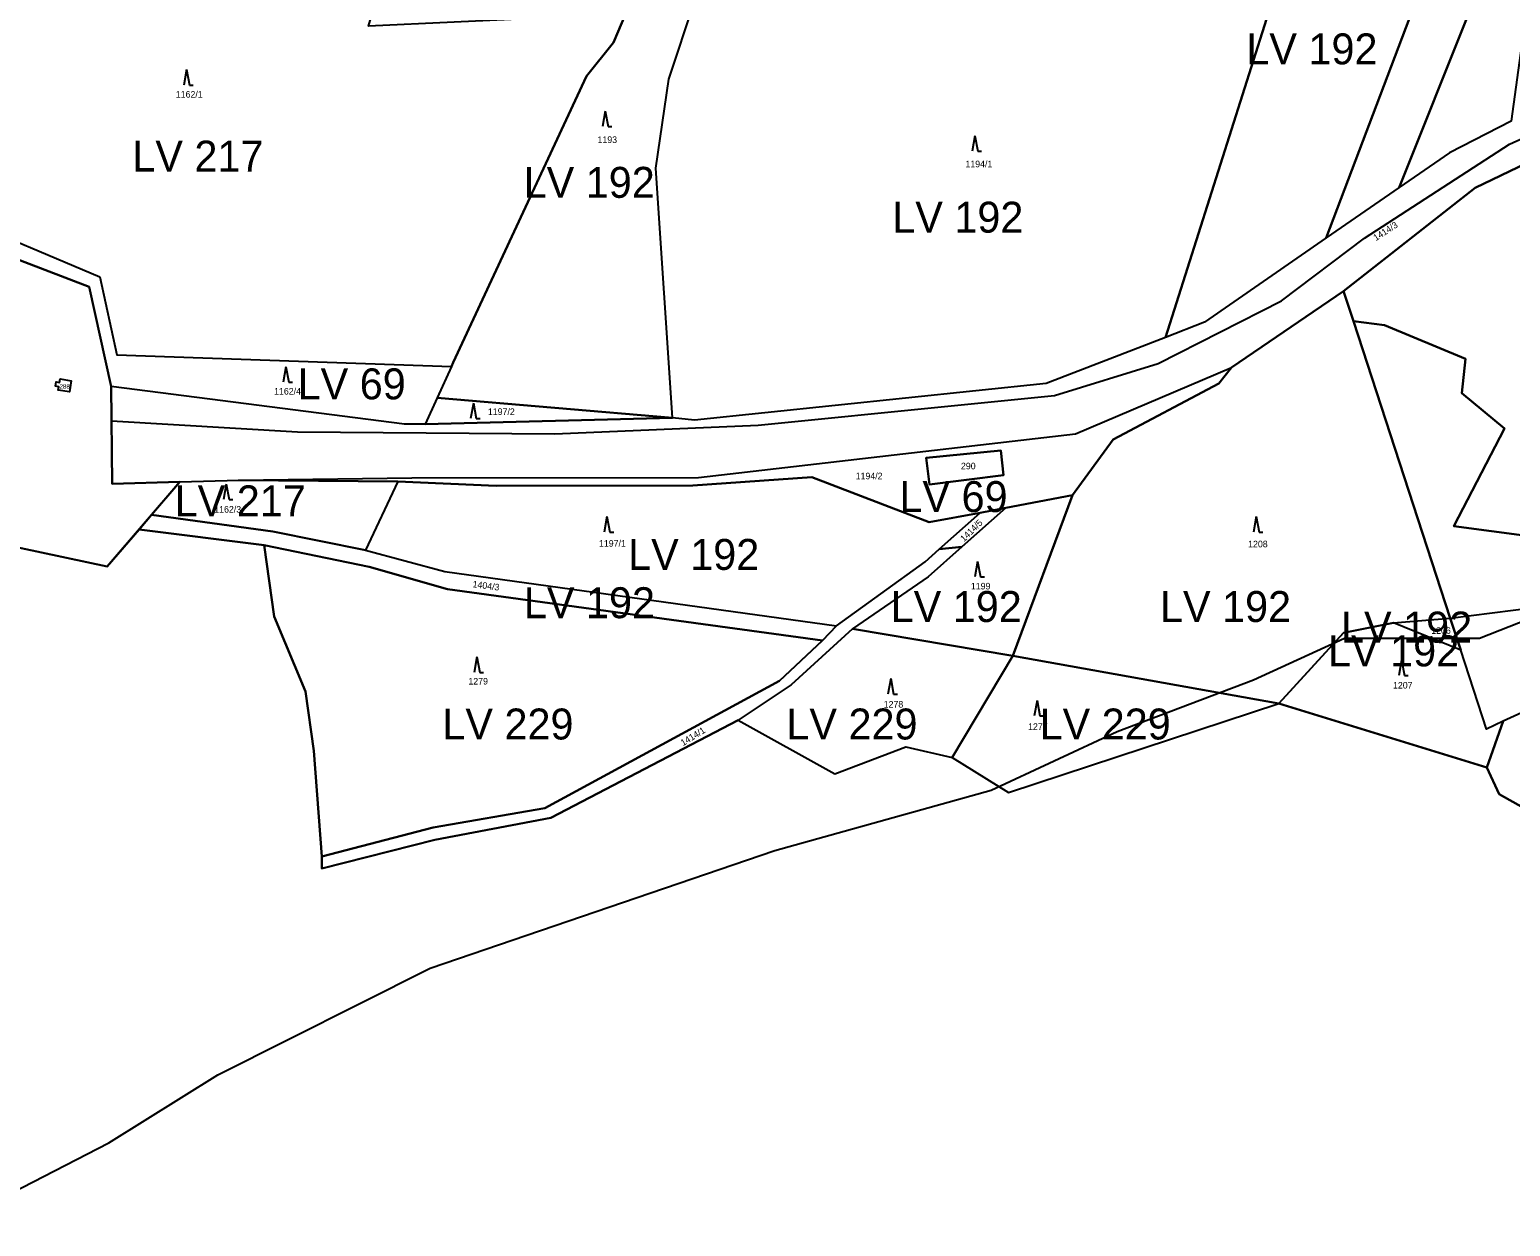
# Model space of a CAD drawing. Extents: x -588699 to -585793, y -1060280 to -1056731.
# Drawn here: x -587524.2 to -587141.3, y -1059806.5 to -1059496.8 of the extents above; entities that cross this region are included whole.
import ezdxf

# ---------------------------------------------------------------- set-up
doc = ezdxf.new("R2010")
doc.units = 0
for name, color, linetype in [('Druh pozemku', 7, 'Continuous'), ('Lesy', 7, 'Continuous'), ('Neřešené', 7, 'Continuous'), ('Parcela nároku', 7, 'Continuous'), ('Silnice', 7, 'Continuous'), ('Vnější obvod_k šeření', 7, 'Continuous'), ('Vnější obvod_převzatý', 7, 'Continuous')]:
    doc.layers.add(name, color=color, linetype=linetype)

msp = doc.modelspace()

# ---------------------------------------------------------------- linework, layer by layer
at = {"layer": 'Druh pozemku'}
for p, q in [((-587483.64, -1059507.18), (-587484.38, -1059511.18)), ((-587483.64, -1059507.18), (-587482.91, -1059511.18)), ((-587482.91, -1059511.18), (-587481.91, -1059511.18)), ((-587375.36, -1059517.91), (-587376.09, -1059521.91)), ((-587375.36, -1059517.91), (-587374.63, -1059521.91)), ((-587374.63, -1059521.91), (-587373.63, -1059521.91)), ((-587279.77, -1059524.26), (-587280.51, -1059528.26)), ((-587279.77, -1059524.26), (-587279.04, -1059528.26)), ((-587279.04, -1059528.26), (-587278.04, -1059528.26)), ((-587457.94, -1059584.03), (-587458.68, -1059588.03)), ((-587457.94, -1059584.03), (-587457.21, -1059588.03)), ((-587457.21, -1059588.03), (-587456.21, -1059588.03)), ((-587409.48, -1059593.43), (-587410.21, -1059597.43)), ((-587409.48, -1059593.43), (-587408.75, -1059597.43)), ((-587408.75, -1059597.43), (-587407.75, -1059597.43)), ((-587473.38, -1059614.4), (-587474.11, -1059618.4)), ((-587473.38, -1059614.4), (-587472.65, -1059618.4)), ((-587472.65, -1059618.4), (-587471.65, -1059618.4)), ((-587374.92, -1059622.83), (-587375.66, -1059626.83)), ((-587374.92, -1059622.83), (-587374.19, -1059626.83)), ((-587207, -1059622.83), (-587207.73, -1059626.83)), ((-587207, -1059622.83), (-587206.27, -1059626.83)), ((-587374.19, -1059626.83), (-587373.19, -1059626.83)), ((-587206.27, -1059626.83), (-587205.27, -1059626.83)), ((-587279.06, -1059634.44), (-587279.8, -1059638.44)), ((-587279.06, -1059634.44), (-587278.33, -1059638.44)), ((-587278.33, -1059638.44), (-587277.33, -1059638.44)), ((-587408.57, -1059659.13), (-587409.31, -1059663.13)), ((-587408.57, -1059659.13), (-587407.84, -1059663.13)), ((-587169.43, -1059659.95), (-587170.17, -1059663.95)), ((-587169.43, -1059659.95), (-587168.7, -1059663.95)), ((-587407.84, -1059663.13), (-587406.84, -1059663.13)), ((-587301.53, -1059664.73), (-587302.27, -1059668.73)), ((-587301.53, -1059664.73), (-587300.8, -1059668.73)), ((-587168.7, -1059663.95), (-587167.7, -1059663.95)), ((-587300.8, -1059668.73), (-587299.8, -1059668.73)), ((-587263.7, -1059670.39), (-587264.44, -1059674.39)), ((-587263.7, -1059670.39), (-587262.97, -1059674.39)), ((-587262.97, -1059674.39), (-587261.97, -1059674.39))]:
    msp.add_line(p, q, dxfattribs=at)
at = {"layer": 'Lesy'}
msp.add_lwpolyline([(-587830.68, -1059643.4), (-587768.32, -1059611.67), (-587746.03, -1059603.7), (-587709.91, -1059596.69), (-587662.88, -1059589.58), (-587665.28, -1059570.37), (-587608.37, -1059561.64), (-587605.34, -1059541.79), (-587594.35, -1059542.05), (-587591.73, -1059541.06), (-587549.58, -1059547.75), (-587508.82, -1059563.39), (-587503.12, -1059589.17), (-587502.92, -1059614.37), (-587485.37, -1059613.84), (-587504.15, -1059635.73), (-587603.75, -1059614.54), (-587695.96, -1059628.96), (-587824.59, -1059655.62)], close=True, dxfattribs=at)
at = {"layer": 'Neřešené'}
msp.add_lwpolyline([(-587292.35, -1059607.65), (-587273.03, -1059605.72), (-587272.39, -1059612.11), (-587291.51, -1059614.48)], close=True, dxfattribs=at)
at = {"layer": 'Parcela nároku'}
for points in [[(-587144.52, -1059384.64), (-587133.01, -1059346.51), (-587118.08, -1059303.27), (-587048.58, -1059316.54), (-587020.31, -1059260.9), (-587008.46, -1059270.51), (-587003.28, -1059281.14), (-586985.82, -1059303.13), (-586963.83, -1059324.3), (-586960.97, -1059331.23), (-586967.8, -1059357.02), (-586969.62, -1059361.59), (-587078.9, -1059331.95), (-587119.83, -1059365.24), (-587141.05, -1059520.54), (-587157.06, -1059528.68), (-587170.06, -1059537.69), (-587133.46, -1059446.06), (-587144.92, -1059434.42), (-587164.2, -1059414.98)], [(-587202.03, -1059486.73), (-587196.03, -1059471.23), (-587181.93, -1059444.07), (-587164.2, -1059414.98), (-587144.92, -1059434.42), (-587188.9, -1059550.73), (-587220.38, -1059572.54), (-587230.52, -1059576.46)], [(-587370.17, -1059492.86), (-587436.61, -1059495.95), (-587427.51, -1059465.05), (-587511.21, -1059436.27), (-587549.97, -1059484.29), (-587584.08, -1059537.87), (-587554.64, -1059542.28), (-587547.11, -1059542.59), (-587543.68, -1059544.92), (-587506.07, -1059560.82), (-587501.64, -1059580.99), (-587415.14, -1059583.98), (-587414.66, -1059582.92), (-587380.23, -1059508.83), (-587373.25, -1059500.13)], [(-587144.92, -1059434.42), (-587133.46, -1059446.06), (-587170.06, -1059537.69), (-587188.9, -1059550.73)], [(-587373.25, -1059500.13), (-587380.23, -1059508.83), (-587414.66, -1059582.92), (-587415.14, -1059583.98), (-587418.81, -1059592.06), (-587357.95, -1059597.3), (-587362.28, -1059532.7), (-587358.91, -1059509.67), (-587352.28, -1059489.62), (-587334.33, -1059453.87), (-587353.89, -1059454.52), (-587370.17, -1059492.86)], [(-587358.91, -1059509.67), (-587352.28, -1059489.62), (-587277.22, -1059473.63), (-587273.06, -1059474.35), (-587202.03, -1059486.73), (-587230.52, -1059576.46), (-587261.33, -1059588.36), (-587352.25, -1059597.84), (-587357.95, -1059597.3), (-587362.28, -1059532.7)], [(-587152.88, -1059581.98), (-587153.88, -1059590.92), (-587142.82, -1059600.04), (-587155.89, -1059625.25), (-587125.4, -1059629.36), (-587121.68, -1059598.65), (-587110.15, -1059586.92), (-587109.34, -1059560.63), (-587122.86, -1059561.53), (-587108.33, -1059527.33), (-587110.39, -1059518.52), (-587150.41, -1059537.73), (-587184.41, -1059564.49), (-587181.88, -1059572.25), (-587173.88, -1059573.26)], [(-587110.15, -1059586.92), (-587121.68, -1059598.65), (-587125.4, -1059629.36), (-587155.89, -1059625.25), (-587142.82, -1059600.04), (-587153.88, -1059590.92), (-587152.88, -1059581.98), (-587173.88, -1059573.26), (-587181.88, -1059572.25), (-587156.82, -1059649.13), (-587113.45, -1059643.6), (-587096.36, -1059609.93), (-587107.78, -1059611.76), (-587104.87, -1059560.13), (-587087.56, -1059557.95), (-587099.48, -1059532.92), (-587104.46, -1059518.59), (-587110.39, -1059518.52), (-587108.33, -1059527.33), (-587122.86, -1059561.53), (-587109.34, -1059560.63)], [(-587104.87, -1059560.13), (-587087.56, -1059557.95), (-587099.48, -1059532.92), (-587104.46, -1059518.59), (-587040.59, -1059519.32), (-587035.21, -1059535.76), (-587027.75, -1059558.57), (-587015.76, -1059597.2), (-587011.41, -1059611.21), (-587010.19, -1059615.13), (-587033.76, -1059625.88), (-587092.75, -1059652.79), (-587143.14, -1059675.76), (-587147.48, -1059677.78), (-587154.14, -1059657.35), (-587156.82, -1059649.13), (-587113.45, -1059643.6), (-587096.36, -1059609.93), (-587107.78, -1059611.76)], [(-587506.07, -1059560.82), (-587501.64, -1059580.99), (-587415.14, -1059583.98), (-587418.81, -1059592.06), (-587421.9, -1059598.86), (-587427.28, -1059598.94), (-587503.12, -1059589.17), (-587508.82, -1059563.39), (-587549.58, -1059547.75), (-587586.62, -1059541.87), (-587584.08, -1059537.87), (-587554.64, -1059542.28), (-587547.11, -1059542.59), (-587543.68, -1059544.92)], [(-587485.37, -1059613.84), (-587502.92, -1059614.37), (-587503.12, -1059589.17), (-587508.82, -1059563.39), (-587549.58, -1059547.75), (-587586.62, -1059541.87), (-587591.73, -1059541.06), (-587594.35, -1059542.05), (-587605.34, -1059541.79), (-587608.37, -1059561.64), (-587610.84, -1059582.32), (-587603.75, -1059614.54), (-587504.15, -1059635.73), (-587495.91, -1059626.13), (-587492.69, -1059622.37)], [(-587216.69, -1059588.38), (-587244.02, -1059602.91), (-587254.49, -1059617.29), (-587269.94, -1059658.83), (-587201.15, -1059671.19), (-587184.41, -1059652.86), (-587171.48, -1059650.28), (-587156.82, -1059649.13), (-587181.88, -1059572.25), (-587184.41, -1059564.49), (-587213.44, -1059584.25)], [(-587425.35, -1059612.75), (-587351.25, -1059612.71), (-587253.74, -1059601.39), (-587213.44, -1059584.25), (-587216.69, -1059588.38), (-587244.02, -1059602.91), (-587254.49, -1059617.29), (-587271.74, -1059620.53), (-587278.45, -1059621.8), (-587291.6, -1059624.27), (-587321.98, -1059612.58), (-587352.7, -1059614.73), (-587403.61, -1059614.83), (-587429.01, -1059613.77), (-587470.12, -1059613.39)], [(-587513.46, -1059587.65), (-587513.9, -1059590.56), (-587516.82, -1059590.12), (-587516.69, -1059589.2), (-587517.55, -1059589.05), (-587517.36, -1059587.94), (-587516.5, -1059588.13), (-587516.33, -1059587.21)], [(-587517.36, -1059587.94), (-587516.5, -1059588.13), (-587516.33, -1059587.21), (-587513.46, -1059587.65), (-587513.9, -1059590.56), (-587516.82, -1059590.12), (-587516.69, -1059589.2), (-587517.55, -1059589.05)], [(-587357.95, -1059597.3), (-587418.81, -1059592.06), (-587421.9, -1059598.86)], [(-587291.51, -1059614.48), (-587272.39, -1059612.11), (-587273.03, -1059605.72), (-587292.35, -1059607.65)], [(-587273.03, -1059605.72), (-587292.35, -1059607.65), (-587291.51, -1059614.48), (-587272.39, -1059612.11)], [(-587403.61, -1059614.83), (-587429.01, -1059613.77), (-587437.37, -1059631.51), (-587416.84, -1059636.99), (-587315.6, -1059651.08), (-587292.66, -1059634.55), (-587288.99, -1059631.26), (-587278.45, -1059621.8), (-587291.6, -1059624.27), (-587321.98, -1059612.58), (-587352.7, -1059614.73)], [(-587492.69, -1059622.37), (-587485.37, -1059613.84), (-587470.12, -1059613.39), (-587429.01, -1059613.77), (-587437.37, -1059631.51), (-587461.3, -1059626.7)], [(-587254.49, -1059617.29), (-587271.74, -1059620.53), (-587283.16, -1059630.67), (-587291.9, -1059638.44), (-587311.4, -1059651.83), (-587269.94, -1059658.83)], [(-587437.37, -1059631.51), (-587416.84, -1059636.99), (-587315.6, -1059651.08), (-587319.19, -1059654.89), (-587416.17, -1059641.61), (-587436.38, -1059635.79), (-587463.54, -1059630.25), (-587495.91, -1059626.13), (-587492.69, -1059622.37), (-587461.3, -1059626.7)], [(-587288.99, -1059631.26), (-587278.45, -1059621.8), (-587271.74, -1059620.53), (-587283.16, -1059630.67)], [(-587092.75, -1059652.79), (-587143.14, -1059675.76), (-587147.34, -1059687.77), (-587144.15, -1059694.61), (-587107.2, -1059715.41), (-587055.43, -1059652.3), (-587051.95, -1059648.06), (-587033.76, -1059625.88)], [(-587436.38, -1059635.79), (-587416.17, -1059641.61), (-587319.19, -1059654.89), (-587330.3, -1059665.35), (-587391.02, -1059698.23), (-587419.89, -1059703.24), (-587448.65, -1059710.74), (-587450.77, -1059683.46), (-587452.87, -1059668.09), (-587460.95, -1059648.68), (-587463.54, -1059630.25)], [(-587292.66, -1059634.55), (-587288.99, -1059631.26), (-587283.16, -1059630.67), (-587291.9, -1059638.44), (-587311.4, -1059651.83), (-587327.31, -1059666.35), (-587341, -1059675.47), (-587389.43, -1059700.77), (-587419.41, -1059706.47), (-587448.65, -1059713.82), (-587448.65, -1059710.74), (-587419.89, -1059703.24), (-587391.02, -1059698.23), (-587330.3, -1059665.35), (-587319.19, -1059654.89), (-587315.6, -1059651.08)], [(-587171.48, -1059650.28), (-587184.41, -1059652.86), (-587201.15, -1059671.19), (-587147.34, -1059687.77), (-587143.14, -1059675.76), (-587147.48, -1059677.78), (-587154.14, -1059657.35)], [(-587156.82, -1059649.13), (-587154.14, -1059657.35), (-587171.48, -1059650.28)], [(-587327.31, -1059666.35), (-587341, -1059675.47), (-587315.96, -1059689.39), (-587297.67, -1059682.36), (-587285.62, -1059685.13), (-587269.94, -1059658.83), (-587311.4, -1059651.83)], [(-587269.94, -1059658.83), (-587285.62, -1059685.13), (-587271.06, -1059694.19), (-587201.15, -1059671.19)]]:
    msp.add_lwpolyline(points, close=True, dxfattribs=at)
for points in [[(-587141.05, -1059520.54), (-587157.06, -1059528.68), (-587170.06, -1059537.69), (-587188.9, -1059550.73), (-587220.38, -1059572.54), (-587230.52, -1059576.46), (-587261.33, -1059588.36), (-587352.25, -1059597.84), (-587357.95, -1059597.3), (-587421.9, -1059598.86), (-587427.28, -1059598.94), (-587503.12, -1059589.17), (-587502.92, -1059614.37), (-587485.37, -1059613.84), (-587470.12, -1059613.39), (-587425.35, -1059612.75), (-587351.25, -1059612.71), (-587253.74, -1059601.39), (-587213.44, -1059584.25), (-587184.41, -1059564.49), (-587150.41, -1059537.73), (-587110.39, -1059518.52)], [(-587603.75, -1059614.54), (-587504.15, -1059635.73), (-587495.91, -1059626.13), (-587463.54, -1059630.25), (-587460.95, -1059648.68), (-587452.87, -1059668.09), (-587450.77, -1059683.46), (-587448.65, -1059710.74), (-587448.65, -1059713.82), (-587419.41, -1059706.47), (-587389.43, -1059700.77), (-587341, -1059675.47), (-587315.96, -1059689.39), (-587297.67, -1059682.36), (-587285.62, -1059685.13), (-587271.06, -1059694.19), (-587201.15, -1059671.19), (-587147.34, -1059687.77), (-587144.15, -1059694.61), (-587107.2, -1059715.41)]]:
    msp.add_lwpolyline(points, dxfattribs=at)
at = {"layer": 'Silnice'}
for p, q in [((-587141.53, -1059526.46), (-587111.86, -1059513)), ((-587179, -1059550.79), (-587141.53, -1059526.46)), ((-587200.44, -1059567), (-587179, -1059550.79)), ((-587232.35, -1059583.21), (-587200.44, -1059567)), ((-587259.22, -1059591.5), (-587232.35, -1059583.21)), ((-587285.95, -1059594.18), (-587259.22, -1059591.5)), ((-587335.81, -1059599.17), (-587285.95, -1059594.18)), ((-587503.05, -1059598.06), (-587454.97, -1059600.91)), ((-587454.97, -1059600.91), (-587388.41, -1059601.41)), ((-587388.41, -1059601.41), (-587335.81, -1059599.17))]:
    msp.add_line(p, q, dxfattribs=at)
at = {"layer": 'Vnější obvod_k šeření'}
msp.add_lwpolyline([(-587545.78, -1059806.46), (-587503.79, -1059784.83), (-587475.53, -1059767.21), (-587420.62, -1059739.63), (-587331.51, -1059709.19), (-587275.57, -1059693.63), (-587242.96, -1059678.41), (-587207.73, -1059665.02), (-587184.16, -1059654.3), (-587149.27, -1059654.23), (-587113.78, -1059640.29), (-587108.9, -1059637.79), (-587096.59, -1059632.86), (-587057.74, -1059623), (-587025.71, -1059612.76)], dxfattribs=at)
at = {"layer": 'Vnější obvod_převzatý'}
for points in [[(-587392.6, -1059142.78), (-587405.57, -1059198.11), (-587413.42, -1059223.98), (-587436.75, -1059272.86), (-587461.72, -1059331.98), (-587488.94, -1059393.28), (-587511.21, -1059436.27), (-587549.97, -1059484.29), (-587584.08, -1059537.87), (-587554.64, -1059542.28), (-587547.11, -1059542.59), (-587543.68, -1059544.92), (-587506.07, -1059560.82), (-587501.64, -1059580.99), (-587415.14, -1059583.98)], [(-587414.9, -1059583.45), (-587380.23, -1059508.83), (-587373.25, -1059500.13), (-587370.17, -1059492.86), (-587353.89, -1059454.52), (-587339.46, -1059413.39), (-587315.81, -1059366), (-587293.33, -1059329.45), (-587274.9, -1059292.25), (-587260, -1059239.72), (-587253.69, -1059214.59), (-587247.38, -1059189.46), (-587237.08, -1059158.04), (-587231.92, -1059142.28)], [(-587429.01, -1059613.77), (-587403.61, -1059614.83), (-587352.7, -1059614.73), (-587321.98, -1059612.58), (-587291.6, -1059624.27), (-587278.45, -1059621.8), (-587271.74, -1059620.53), (-587254.49, -1059617.29), (-587244.02, -1059602.91), (-587216.69, -1059588.38), (-587213.44, -1059584.25)], [(-586938.9, -1059595.11), (-587003.73, -1059627.3), (-587020.71, -1059639.44), (-587051.95, -1059648.06), (-587055.43, -1059652.3), (-587107.2, -1059715.41), (-587144.15, -1059694.61), (-587147.34, -1059687.77), (-587201.15, -1059671.19), (-587269.94, -1059658.83), (-587311.4, -1059651.83), (-587327.31, -1059666.35), (-587341, -1059675.47)], [(-587429.01, -1059613.77), (-587437.37, -1059631.51), (-587461.3, -1059626.7), (-587492.69, -1059622.37)]]:
    msp.add_lwpolyline(points, dxfattribs=at)

# ---------------------------------------------------------------- texts
at = {"layer": 'Parcela nároku'}
for s, height, p in [('1162/1', 1.7, (-587486.43, -1059514.42)), ('1193', 1.7, (-587377.37, -1059526.15)), ('1194/1', 1.7, (-587282.22, -1059532.44)), ('288', 1.14, (-587516.48, -1059589.72)), ('1162/4', 1.7, (-587461.01, -1059591.24)), ('1197/2', 1.7, (-587405.72, -1059596.52)), ('1194/2', 1.7, (-587310.61, -1059613.16)), ('290', 1.7, (-587283.38, -1059610.58)), ('1162/3', 1.7, (-587476.48, -1059621.79)), ('1197/1', 1.7, (-587376.99, -1059630.6)), ('1208', 1.7, (-587209.11, -1059630.76)), ('1199', 1.7, (-587280.81, -1059641.66)), ('1206', 1.7, (-587161.77, -1059653.15)), ('1279', 1.7, (-587410.76, -1059666.26)), ('1207', 1.7, (-587171.65, -1059667.3)), ('1278', 1.7, (-587303.36, -1059672.22)), ('1277', 1.7, (-587266.02, -1059678))]:
    msp.add_text(s, height=height, dxfattribs=at).set_placement(p)
for s, rotation, p in [('1414/3', 32.9583, (-587176.06, -1059551.57)), ('1414/5', 44.3, (-587282.59, -1059629.46)), ('1404/3', 352.4495, (-587409.75, -1059641.08)), ('1414/1', 31.5051, (-587355.24, -1059682.22))]:
    msp.add_text(s, height=1.7, rotation=rotation, dxfattribs=at).set_placement(p)
at = {"layer": 'Vnější obvod_převzatý'}
for s, p in [('LV 192', (-587209.57, -1059505.81)), ('LV 217', (-587497.67, -1059533.55)), ('LV 192', (-587396.47, -1059540.34)), ('LV 192', (-587301.14, -1059549.35)), ('LV 69', (-587454.92, -1059592.47)), ('LV 217', (-587486.72, -1059622.74)), ('LV 69', (-587299.28, -1059621.64)), ('LV 192', (-587369.45, -1059636.6)), ('LV 192', (-587396.41, -1059649.1)), ('LV 192', (-587301.56, -1059650.08)), ('LV 192', (-587231.91, -1059650.08)), ('LV 192', (-587185.08, -1059655.4)), ('LV 192', (-587188.44, -1059661.57)), ('LV 229', (-587417.49, -1059680.48)), ('LV 229', (-587328.52, -1059680.48)), ('LV 229', (-587263.04, -1059680.48))]:
    msp.add_text(s, height=8, dxfattribs=at).set_placement(p)

doc.saveas('drawing.dxf')
